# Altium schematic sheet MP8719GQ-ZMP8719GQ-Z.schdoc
size 127 x 101 mm
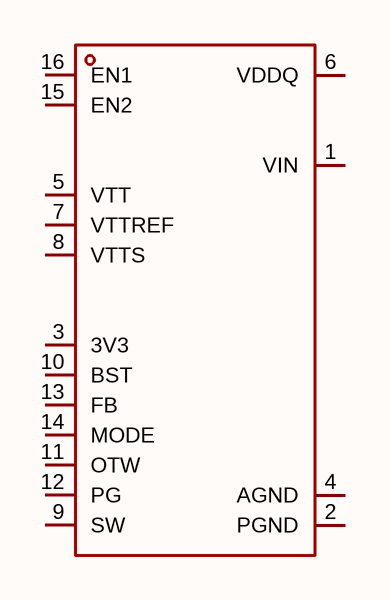
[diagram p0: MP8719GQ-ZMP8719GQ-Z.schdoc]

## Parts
U?  mp8719gq-z  [QFN-16_L3.0-W3.0_IS6630A]  (value not drawn)

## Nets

Not connected (* = marked no-connect by the designer): U? 1(VIN) 2(PGND) 3(3V3) 4(AGND) 5(VTT) 6(VDDQ) 7(VTTREF) 8(VTTS) 9(SW) 10(BST) 11(OTW) 12(PG) 13(FB) 14(MODE) 15(EN2) 16(EN1)

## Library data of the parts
U? = mp8719gq-z: 功能类型:降压型;工作电压:4.5V~26V;输出电压:600mV~3.3V;输出电流:12A;输出类型:可调;; Manufacturer: MPS(芯源); AddInBom: yes; ModelId: 41d15a9a6a994ea5bb8430cdb29a2603; ModelTransform: 118.18874,118.18874,0,0,0,0,-0.987,-0.002,0; Function: 降压型; Output Current: 12A; Frequency - Switching: 500kHz~700kHz; Synchronous Rectifier: 是; Number of Outputs: 1; Topology: 降压式; Quiescent Current: 135uA; Switch tube (built-in/external): 内置; Output Type: 可调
